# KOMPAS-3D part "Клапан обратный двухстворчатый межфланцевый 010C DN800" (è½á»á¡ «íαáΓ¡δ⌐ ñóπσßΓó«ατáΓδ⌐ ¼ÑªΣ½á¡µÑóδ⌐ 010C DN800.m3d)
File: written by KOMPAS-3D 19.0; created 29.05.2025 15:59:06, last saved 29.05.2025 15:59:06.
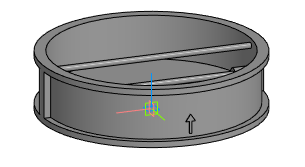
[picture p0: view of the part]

Document properties: Полное имя файла: E:\Dendor Работа Сачек\3D для проекитирвщиков\5.2 Тип 010C, 010C.Y Клапан обратный двухстворчатый межфланцевый\stp_Клапан обратный двухстворчатый межфланцевый 010C\Клапан обратный двухстворчатый межфланцевый 010C DN800.m3d

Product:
- Part/product: Клапан обратный двухстворчатый межфланцевый 010C DN800

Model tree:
1. Операция без истории:1  (labels: Клапан обратный двухстворчатый межфланцевый 010C DN800)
